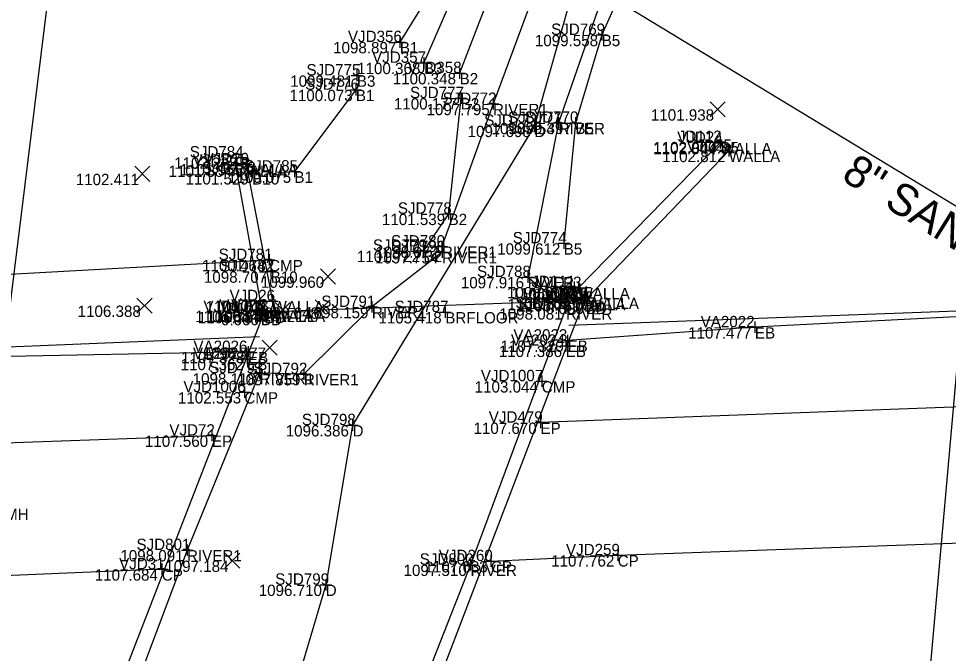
# Model space of a CAD drawing. Extents: x 1629915 to 1630675, y 484401 to 484601.
# Drawn here: x 1630255.7 to 1630337.7, y 484481.8 to 484537.9 of the extents above; entities that cross this region are included whole.
import ezdxf

# ---------------------------------------------------------------- set-up
doc = ezdxf.new("R2010")
doc.units = 0
for name, color, linetype in [('BR_X_Sub_Foot_Object', 7, 'Continuous'), ('BR_X_Sub_Object', 7, 'Continuous'), ('BR_X_SV_Abut', 7, 'Continuous'), ('BR_X_SV_Abut_Text', 7, 'Continuous'), ('BR_X_SV_Deck_Floor', 7, 'Continuous'), ('BR_X_SV_Deck_Top', 7, 'Continuous'), ('DR_X_Ditch', 7, 'Continuous'), ('DR_X_Storm_Sewer', 7, 'Continuous'), ('HY_X_Water_Edge', 7, 'Continuous'), ('PV_X_COP', 7, 'Continuous'), ('PV_X_EOP', 7, 'Continuous'), ('PV_X_Shoulder_Aggregate', 7, 'Continuous'), ('RD_X_GR_Rt', 7, 'Continuous'), ('SV_X_Break_Lines', 7, 'Continuous'), ('SV_X_Random_Point', 7, 'Continuous'), ('SV_X_Shot_Marker', 7, 'Continuous'), ('SV_X_Text_Comment', 7, 'Continuous'), ('SV_X_Text_Elevation', 7, 'Continuous'), ('SV_X_Text_Name', 7, 'Continuous'), ('TX_X_20', 7, 'Continuous'), ('UT_X_Sanitary_Line', 7, 'Continuous')]:
    doc.layers.add(name, color=color, linetype=linetype)

msp = doc.modelspace()

# ---------------------------------------------------------------- linework, layer by layer
at = {"layer": 'BR_X_Sub_Foot_Object'}
msp.add_line((1630334.981, 484467.226), (1630346.372, 484596.321), dxfattribs=at)
at = {"layer": 'BR_X_SV_Abut'}
msp.add_line((1630318.36, 484526.182), (1630305.897, 484513.214), dxfattribs=at)
for points in [[(1630305.897, 484513.214), (1630304.711, 484513.112), (1630305.093, 484514.078), (1630317.606, 484526.882), (1630318.36, 484526.182)], [(1630277.181, 484512.086), (1630274.846, 484524.883), (1630275.777, 484525.003), (1630278.092, 484512.916), (1630278.21, 484512.086)]]:
    msp.add_lwpolyline(points, dxfattribs=at)
at = {"layer": 'BR_X_SV_Deck_Floor'}
msp.add_line((1630293.34, 484511.948), (1630293.34, 484511.948), dxfattribs=at)
at = {"layer": 'BR_X_SV_Deck_Top'}
msp.add_lwpolyline([(1630288.791, 484468.471), (1630260.332, 484468), (1630277.393, 484511.967), (1630305.582, 484512.994), (1630288.334, 484467.836)], dxfattribs=at)
at = {"layer": 'DR_X_Ditch'}
msp.add_lwpolyline([(1630312.285, 484563.174), (1630306.638, 484548.008), (1630304.593, 484540.369), (1630301.212, 484528.393), (1630285.162, 484501.971), (1630282.791, 484487.89), (1630276.09, 484465.226), (1630270.913, 484444.523), (1630257.639, 484422.19), (1630254.188, 484411.475)], dxfattribs=at)
at = {"layer": 'DR_X_Storm_Sewer'}
msp.add_line((1630034.139, 484503.088), (1630277.798, 484516.548), dxfattribs=at)
at = {"layer": 'HY_X_Water_Edge'}
for points in [[(1630309.149, 484564.014), (1630303.907, 484548.371), (1630301.335, 484540.498), (1630297.554, 484530.327), (1630293.047, 484517.737), (1630293.065, 484517.242), (1630286.863, 484512.402), (1630280.864, 484506.48), (1630276.95, 484506.557), (1630270.552, 484490.946), (1630261.424, 484466.626), (1630255.81, 484461.657), (1630255.926, 484458.148), (1630258.606, 484455.59), (1630264.105, 484457.697), (1630265.615, 484457.846), (1630266.742, 484455.334), (1630264.827, 484450.845), (1630263.176, 484437.258), (1630258.725, 484424.768), (1630254.124, 484415.998)], [(1630315.117, 484563.934), (1630310.133, 484547.118), (1630307.022, 484539.287), (1630303.337, 484528.643), (1630300.614, 484515.043), (1630303.987, 484512.284), (1630295.569, 484489.654), (1630286.814, 484467.342), (1630288.813, 484458.618), (1630286.633, 484457.39), (1630280.042, 484444.765), (1630267.68, 484419.987), (1630256.457, 484407.968)]]:
    msp.add_lwpolyline(points, dxfattribs=at)
at = {"layer": 'PV_X_COP'}
for points in [[(1630297.366, 484489.973), (1630308.553, 484490.492), (1630361.839, 484492.402), (1630403.565, 484493.662), (1630440.464, 484494.931), (1630486.149, 484496.207), (1630529.234, 484497.459), (1630568.325, 484498.484), (1630611.926, 484499.834), (1630649.713, 484500.97)], [(1630268.327, 484489.246), (1630243.236, 484488.193), (1630219.614, 484487.396), (1630181.886, 484485.929), (1630141.907, 484484.591), (1630101.847, 484483.155), (1630058.972, 484481.674), (1630018.452, 484480.335), (1629978.036, 484478.791), (1629939.203, 484477.211)]]:
    msp.add_lwpolyline(points, dxfattribs=at)
at = {"layer": 'PV_X_EOP'}
for points in [[(1630649.544, 484512.337), (1630611.095, 484510.961), (1630568.311, 484509.618), (1630527.921, 484508.555), (1630486.049, 484507.685), (1630439.965, 484506.412), (1630403.104, 484505.478), (1630361.875, 484504.434), (1630301.74, 484502.192)], [(1629938.787, 484488.624), (1629977.755, 484490.201), (1630018.109, 484491.66), (1630058.596, 484492.972), (1630101.458, 484494.639), (1630141.527, 484496.094), (1630181.4, 484497.615), (1630219.199, 484499.135), (1630242.799, 484500.003), (1630272.749, 484501.051)]]:
    msp.add_lwpolyline(points, dxfattribs=at)
at = {"layer": 'PV_X_Shoulder_Aggregate'}
for points in [[(1630609.295, 484512.622), (1630601.375, 484512.79), (1630594.371, 484513.028), (1630564.661, 484511.714), (1630557.668, 484510.64), (1630535.062, 484510.052), (1630513.96, 484509.735), (1630489.956, 484510.39), (1630468.462, 484511.02), (1630445.091, 484511.198), (1630420.706, 484511.45), (1630393.49, 484511.943), (1630369.145, 484512.288), (1630344.7, 484511.845), (1630320.659, 484510.608), (1630304.125, 484509.436), (1630303.965, 484508.981)], [(1630275.858, 484507.82), (1630275.935, 484508.43), (1630251.773, 484507.981), (1630226.056, 484507.184), (1630204.993, 484506.289), (1630180.178, 484504.732), (1630155.752, 484502.786), (1630130.505, 484501.377), (1630107.341, 484499.869), (1630082.614, 484498.877), (1630057.423, 484497.854), (1630056.684, 484498.178), (1630055.974, 484498.791), (1630036.737, 484497.117), (1630036.516, 484496.78), (1630005.439, 484492.996), (1629981.146, 484491.329), (1629968.094, 484490.842), (1629967.166, 484490.748), (1629965.306, 484491.801), (1629947.85, 484491.524), (1629935.773, 484490.2), (1629921.037, 484489.433)]]:
    msp.add_lwpolyline(points, dxfattribs=at)
at = {"layer": 'RD_X_GR_Rt'}
for points in [[(1630416.419, 484512.818), (1630392.125, 484513.02), (1630367.206, 484513.077), (1630304.229, 484510.755)], [(1630276.942, 484509.755), (1630213.199, 484507.144), (1630188.359, 484506.044), (1630165.142, 484504.69)]]:
    msp.add_lwpolyline(points, dxfattribs=at)
at = {"layer": 'SV_X_Break_Lines'}
for points in [[(1630296.417, 484563.601), (1630295.615, 484557.584), (1630296.178, 484554.459), (1630296.937, 484552.722), (1630292.991, 484547.948), (1630292.183, 484542.654), (1630292.496, 484540.935), (1630289.335, 484535.783)], [(1630304.314, 484563.932), (1630300.799, 484552.969), (1630299.066, 484544.645), (1630294.605, 484533.045)], [(1630314.711, 484561.886), (1630311.942, 484547.182), (1630307.141, 484536.414), (1630304.819, 484528.662), (1630303.788, 484518.017)], [(1630297.86, 484555.334), (1630298.878, 484552.674), (1630295.673, 484546.879), (1630294.364, 484540.646), (1630291.461, 484533.951)], [(1630285.452, 484531.568), (1630280.033, 484524.355)], [(1630294.699, 484530.831), (1630293.632, 484520.628), (1630291.414, 484517.361)]]:
    msp.add_lwpolyline(points, dxfattribs=at)
at = {"layer": 'SV_X_Random_Point'}
for p, q in [((1630316.712, 484529.177), (1630318.045, 484530.512)), ((1630316.712, 484530.512), (1630318.045, 484529.177)), ((1630265.945, 484523.483), (1630267.278, 484524.818)), ((1630265.945, 484524.818), (1630267.278, 484523.483)), ((1630282.319, 484514.424), (1630283.653, 484515.759)), ((1630282.319, 484515.759), (1630283.653, 484514.424)), ((1630266.132, 484511.855), (1630267.465, 484513.19)), ((1630266.132, 484513.19), (1630267.465, 484511.855)), ((1630278.319, 484511.46), (1630279.652, 484512.795)), ((1630278.319, 484512.795), (1630279.652, 484511.46)), ((1630281.851, 484511.691), (1630283.185, 484513.026)), ((1630281.851, 484513.026), (1630283.185, 484511.691)), ((1630277.177, 484508.147), (1630278.51, 484509.482)), ((1630277.177, 484509.482), (1630278.51, 484508.147)), ((1630273.888, 484489.346), (1630275.221, 484490.681)), ((1630273.888, 484490.681), (1630275.221, 484489.346))]:
    msp.add_line(p, q, dxfattribs=at)
at = {"layer": 'SV_X_Shot_Marker'}
for p, q in [((1630289.335, 484536.283), (1630289.335, 484535.283)), ((1630306.641, 484536.414), (1630307.641, 484536.414)), ((1630307.141, 484536.914), (1630307.141, 484535.914)), ((1630307.141, 484536.414), (1630307.141, 484536.414)), ((1630288.835, 484535.783), (1630289.835, 484535.783)), ((1630289.335, 484535.783), (1630289.335, 484535.783)), ((1630290.961, 484533.951), (1630291.961, 484533.951)), ((1630291.461, 484534.451), (1630291.461, 484533.451)), ((1630291.461, 484533.951), (1630291.461, 484533.951)), ((1630285.538, 484533.334), (1630285.538, 484532.334)), ((1630294.105, 484533.045), (1630295.105, 484533.045)), ((1630294.605, 484533.545), (1630294.605, 484532.545)), ((1630294.605, 484533.045), (1630294.605, 484533.045)), ((1630285.038, 484532.834), (1630286.038, 484532.834)), ((1630285.538, 484532.834), (1630285.538, 484532.834)), ((1630284.952, 484531.568), (1630285.952, 484531.568)), ((1630285.452, 484532.068), (1630285.452, 484531.068)), ((1630285.452, 484531.568), (1630285.452, 484531.568)), ((1630294.699, 484531.331), (1630294.699, 484530.331)), ((1630294.199, 484530.831), (1630295.199, 484530.831)), ((1630294.699, 484530.831), (1630294.699, 484530.831)), ((1630297.554, 484530.827), (1630297.554, 484529.827)), ((1630297.054, 484530.327), (1630298.054, 484530.327)), ((1630297.554, 484530.327), (1630297.554, 484530.327)), ((1630301.212, 484528.893), (1630301.212, 484527.893)), ((1630303.337, 484529.143), (1630303.337, 484528.143)), ((1630304.819, 484529.162), (1630304.819, 484528.162)), ((1630300.712, 484528.393), (1630301.712, 484528.393)), ((1630301.212, 484528.393), (1630301.212, 484528.393)), ((1630302.837, 484528.643), (1630303.837, 484528.643)), ((1630303.337, 484528.643), (1630303.337, 484528.643)), ((1630304.319, 484528.662), (1630305.319, 484528.662)), ((1630304.819, 484528.662), (1630304.819, 484528.662)), ((1630317.605, 484527.466), (1630317.605, 484526.466)), ((1630317.606, 484527.382), (1630317.606, 484526.382)), ((1630317.105, 484526.966), (1630318.105, 484526.966)), ((1630317.106, 484526.882), (1630318.106, 484526.882)), ((1630317.605, 484526.966), (1630317.605, 484526.966)), ((1630317.606, 484526.882), (1630317.606, 484526.882)), ((1630318.36, 484526.682), (1630318.36, 484525.682)), ((1630274.787, 484525.596), (1630275.787, 484525.596)), ((1630275.287, 484526.096), (1630275.287, 484525.096)), ((1630275.287, 484525.596), (1630275.287, 484525.596)), ((1630317.86, 484526.182), (1630318.86, 484526.182)), ((1630318.36, 484526.182), (1630318.36, 484526.182)), ((1630274.346, 484524.883), (1630275.346, 484524.883)), ((1630274.846, 484525.383), (1630274.846, 484524.383)), ((1630274.846, 484524.883), (1630274.846, 484524.883)), ((1630275.277, 484525.003), (1630276.277, 484525.003)), ((1630275.777, 484525.503), (1630275.777, 484524.503)), ((1630275.777, 484525.003), (1630275.777, 484525.003)), ((1630280.033, 484524.855), (1630280.033, 484523.855)), ((1630275.806, 484524.208), (1630276.806, 484524.208)), ((1630276.306, 484524.708), (1630276.306, 484523.708)), ((1630276.306, 484524.208), (1630276.306, 484524.208)), ((1630279.533, 484524.355), (1630280.533, 484524.355)), ((1630280.033, 484524.355), (1630280.033, 484524.355)), ((1630293.632, 484521.128), (1630293.632, 484520.128)), ((1630293.132, 484520.628), (1630294.132, 484520.628)), ((1630293.632, 484520.628), (1630293.632, 484520.628)), ((1630293.047, 484518.237), (1630293.047, 484517.237)), ((1630303.788, 484518.517), (1630303.788, 484517.517)), ((1630291.414, 484517.861), (1630291.414, 484516.861)), ((1630292.547, 484517.737), (1630293.547, 484517.737)), ((1630293.047, 484517.737), (1630293.047, 484517.737)), ((1630293.065, 484517.742), (1630293.065, 484516.742)), ((1630303.288, 484518.017), (1630304.288, 484518.017)), ((1630303.788, 484518.017), (1630303.788, 484518.017)), ((1630277.298, 484516.548), (1630278.298, 484516.548)), ((1630277.798, 484517.048), (1630277.798, 484516.048)), ((1630277.798, 484516.548), (1630277.798, 484516.548)), ((1630290.914, 484517.361), (1630291.914, 484517.361)), ((1630291.414, 484517.361), (1630291.414, 484517.361)), ((1630292.565, 484517.242), (1630293.565, 484517.242)), ((1630293.065, 484517.242), (1630293.065, 484517.242)), ((1630277.935, 484516.036), (1630277.935, 484515.036)), ((1630277.435, 484515.536), (1630278.435, 484515.536)), ((1630277.935, 484515.536), (1630277.935, 484515.536)), ((1630300.114, 484515.043), (1630301.114, 484515.043)), ((1630300.614, 484515.543), (1630300.614, 484514.543)), ((1630300.614, 484515.043), (1630300.614, 484515.043)), ((1630304.2, 484514.161), (1630305.2, 484514.161)), ((1630304.7, 484514.661), (1630304.7, 484513.661)), ((1630304.7, 484514.161), (1630304.7, 484514.161)), ((1630305.093, 484514.578), (1630305.093, 484513.578)), ((1630278.092, 484513.416), (1630278.092, 484512.416)), ((1630304.593, 484514.078), (1630305.593, 484514.078)), ((1630304.711, 484513.612), (1630304.711, 484512.612)), ((1630305.093, 484514.078), (1630305.093, 484514.078)), ((1630305.582, 484513.494), (1630305.582, 484512.494)), ((1630305.728, 484513.269), (1630305.728, 484512.269)), ((1630305.897, 484513.714), (1630305.897, 484512.714)), ((1630277.181, 484512.564), (1630277.181, 484511.564)), ((1630277.393, 484512.467), (1630277.393, 484511.467)), ((1630277.592, 484512.916), (1630278.592, 484512.916)), ((1630278.092, 484512.916), (1630278.092, 484512.916)), ((1630278.21, 484512.586), (1630278.21, 484511.586)), ((1630286.863, 484512.902), (1630286.863, 484511.902)), ((1630293.34, 484512.448), (1630293.34, 484511.448)), ((1630303.987, 484512.784), (1630303.987, 484511.784)), ((1630304.211, 484513.112), (1630305.211, 484513.112)), ((1630304.711, 484513.112), (1630304.711, 484513.112)), ((1630305.082, 484512.994), (1630306.082, 484512.994)), ((1630305.228, 484512.769), (1630306.228, 484512.769)), ((1630305.397, 484513.214), (1630306.397, 484513.214)), ((1630305.582, 484512.994), (1630305.582, 484512.994)), ((1630305.728, 484512.769), (1630305.728, 484512.769)), ((1630305.897, 484513.214), (1630305.897, 484513.214)), ((1630276.573, 484511.782), (1630277.573, 484511.782)), ((1630276.681, 484512.064), (1630277.681, 484512.064)), ((1630276.893, 484511.967), (1630277.893, 484511.967)), ((1630277.073, 484512.282), (1630277.073, 484511.282)), ((1630277.073, 484511.782), (1630277.073, 484511.782)), ((1630277.181, 484512.064), (1630277.181, 484512.064)), ((1630277.393, 484511.967), (1630277.393, 484511.967)), ((1630277.71, 484512.086), (1630278.71, 484512.086)), ((1630278.21, 484512.086), (1630278.21, 484512.086)), ((1630286.363, 484512.402), (1630287.363, 484512.402)), ((1630286.863, 484512.402), (1630286.863, 484512.402)), ((1630292.84, 484511.948), (1630293.84, 484511.948)), ((1630293.34, 484511.948), (1630293.34, 484511.948)), ((1630303.487, 484512.284), (1630304.487, 484512.284)), ((1630303.987, 484512.284), (1630303.987, 484512.284)), ((1630320.659, 484511.108), (1630320.659, 484510.108)), ((1630320.159, 484510.608), (1630321.159, 484510.608)), ((1630320.659, 484510.608), (1630320.659, 484510.608)), ((1630303.625, 484509.436), (1630304.625, 484509.436)), ((1630303.965, 484509.481), (1630303.965, 484508.481)), ((1630304.125, 484509.936), (1630304.125, 484508.936)), ((1630304.125, 484509.436), (1630304.125, 484509.436)), ((1630275.435, 484508.43), (1630276.435, 484508.43)), ((1630275.935, 484508.93), (1630275.935, 484507.93)), ((1630275.935, 484508.43), (1630275.935, 484508.43)), ((1630303.465, 484508.981), (1630304.465, 484508.981)), ((1630303.965, 484508.981), (1630303.965, 484508.981)), ((1630275.358, 484507.82), (1630276.358, 484507.82)), ((1630275.858, 484508.32), (1630275.858, 484507.32)), ((1630275.858, 484507.82), (1630275.858, 484507.82)), ((1630276.95, 484507.057), (1630276.95, 484506.057)), ((1630280.864, 484506.98), (1630280.864, 484505.98)), ((1630276.45, 484506.557), (1630277.45, 484506.557)), ((1630276.95, 484506.557), (1630276.95, 484506.557)), ((1630280.364, 484506.48), (1630281.364, 484506.48)), ((1630280.864, 484506.48), (1630280.864, 484506.48)), ((1630301.853, 484506.347), (1630301.853, 484505.347)), ((1630275.613, 484505.379), (1630275.613, 484504.379)), ((1630301.353, 484505.847), (1630302.353, 484505.847)), ((1630301.853, 484505.847), (1630301.853, 484505.847)), ((1630275.113, 484504.879), (1630276.113, 484504.879)), ((1630275.613, 484504.879), (1630275.613, 484504.879)), ((1630301.74, 484502.692), (1630301.74, 484501.692)), ((1630284.662, 484501.971), (1630285.662, 484501.971)), ((1630285.162, 484502.471), (1630285.162, 484501.471)), ((1630285.162, 484501.971), (1630285.162, 484501.971)), ((1630301.24, 484502.192), (1630302.24, 484502.192)), ((1630301.74, 484502.192), (1630301.74, 484502.192)), ((1630272.249, 484501.051), (1630273.249, 484501.051)), ((1630272.749, 484501.551), (1630272.749, 484500.551)), ((1630272.749, 484501.051), (1630272.749, 484501.051)), ((1630270.552, 484491.446), (1630270.552, 484490.446)), ((1630270.052, 484490.946), (1630271.052, 484490.946)), ((1630270.552, 484490.946), (1630270.552, 484490.946)), ((1630297.366, 484490.473), (1630297.366, 484489.473)), ((1630308.053, 484490.492), (1630309.053, 484490.492)), ((1630308.553, 484490.992), (1630308.553, 484489.992)), ((1630308.553, 484490.492), (1630308.553, 484490.492)), ((1630268.327, 484489.746), (1630268.327, 484488.746)), ((1630295.069, 484489.654), (1630296.069, 484489.654)), ((1630295.569, 484490.154), (1630295.569, 484489.154)), ((1630295.569, 484489.654), (1630295.569, 484489.654)), ((1630296.866, 484489.973), (1630297.866, 484489.973)), ((1630297.366, 484489.973), (1630297.366, 484489.973)), ((1630267.827, 484489.246), (1630268.827, 484489.246)), ((1630268.327, 484489.246), (1630268.327, 484489.246)), ((1630282.291, 484487.89), (1630283.291, 484487.89)), ((1630282.791, 484488.39), (1630282.791, 484487.39)), ((1630282.791, 484487.89), (1630282.791, 484487.89))]:
    msp.add_line(p, q, dxfattribs=at)
at = {"layer": 'UT_X_Sanitary_Line'}
msp.add_lwpolyline([(1629930.746, 484483.734), (1630048.132, 484488.308), (1630252.717, 484494.605), (1630261.76, 484567.793), (1630373.422, 484500.095), (1630654.857, 484509.349)], dxfattribs=at)

# ---------------------------------------------------------------- texts
at = {"layer": 'BR_X_Sub_Object'}
for s, p in [('VJD24', (1630313.802, 484526.882)), ('1102.844', (1630311.685, 484525.882)), ('WALLA', (1630317.606, 484525.882)), ('VJD30', (1630271.051, 484524.883)), ('VJD29', (1630272.012, 484525.003)), ('1102.812', (1630312.488, 484525.182)), ('WALLA', (1630318.36, 484525.182)), ('1101.884', (1630268.926, 484523.883)), ('1101.955', (1630269.909, 484524.003)), ('WALLA', (1630274.846, 484523.883)), ('WALLA', (1630275.777, 484524.003)), ('VJD23', (1630301.347, 484514.078)), ('1106.670', (1630299.181, 484513.078)), ('VJD22', (1630300.956, 484513.112)), ('VJD21', (1630302.134, 484513.214)), ('VJD26', (1630274.306, 484512.916)), ('VJD1001', (1630300.222, 484512.994)), ('JD108', (1630301.959, 484512.769)), ('WALLA', (1630305.093, 484513.078)), ('VJD1000', (1630272.001, 484511.967)), ('1106.616', (1630272.19, 484511.916)), ('JD107', (1630273.308, 484511.782)), ('VJD28', (1630273.399, 484512.064)), ('VJD27', (1630274.432, 484512.086)), ('WALLA', (1630278.092, 484511.916)), ('SJD787', (1630288.869, 484511.948)), ('1106.709', (1630298.829, 484512.112)), ('1106.769', (1630299.7, 484511.994)), ('1106.636', (1630299.995, 484512.214)), ('0.000', (1630302.211, 484511.769)), ('WALLA', (1630304.711, 484512.112)), ('BD', (1630305.582, 484511.994)), ('BD', (1630305.728, 484511.769)), ('WALLA', (1630305.897, 484512.214)), ('1106.644', (1630271.261, 484511.064)), ('1106.787', (1630271.499, 484510.967)), ('1106.647', (1630272.316, 484511.086)), ('0.000', (1630273.555, 484510.782)), ('BD', (1630277.073, 484510.782)), ('WALLA', (1630277.181, 484511.064)), ('BD', (1630277.393, 484510.967)), ('WALLA', (1630278.21, 484511.086)), ('1105.418', (1630287.441, 484510.948)), ('BRFLOOR', (1630293.34, 484510.948))]:
    msp.add_text(s, height=1, dxfattribs=at).set_placement(p)
at = {"layer": 'BR_X_SV_Abut_Text'}
msp.add_text('VJD25', height=1, dxfattribs=at).set_placement((1630314.608, 484526.182))
at = {"layer": 'SV_X_Text_Comment'}
for s, p in [('B5', (1630307.141, 484535.414)), ('B1', (1630289.335, 484534.783)), ('B3', (1630291.461, 484532.951)), ('B2', (1630294.605, 484532.045)), ('B3', (1630285.538, 484531.834)), ('B1', (1630285.452, 484530.568)), ('B2', (1630294.699, 484529.831)), ('RIVER1', (1630297.554, 484529.327)), ('D', (1630301.212, 484527.393)), ('RIVER', (1630303.337, 484527.643)), ('B5', (1630304.819, 484527.662)), ('B5', (1630317.605, 484525.966)), ('B', (1630275.287, 484524.596)), ('B10', (1630276.306, 484523.208)), ('B1', (1630280.033, 484523.355)), ('B2', (1630293.632, 484519.628)), ('B2', (1630291.414, 484516.361)), ('RIVER1', (1630293.047, 484516.737)), ('B5', (1630303.788, 484517.017)), ('CMP', (1630277.798, 484515.548)), ('RIVER1', (1630293.065, 484516.242)), ('B10', (1630277.935, 484514.536)), ('RIVER', (1630300.614, 484514.043)), ('B5', (1630304.7, 484513.161)), ('RIVER1', (1630286.863, 484511.402)), ('RIVER', (1630303.987, 484511.284)), ('EB', (1630320.659, 484509.608)), ('EB', (1630304.125, 484508.436)), ('EB', (1630275.935, 484507.43)), ('EB', (1630303.965, 484507.981)), ('EB', (1630275.858, 484506.82)), ('RIVER1', (1630276.95, 484505.557)), ('RIVER1', (1630280.864, 484505.48)), ('CMP', (1630301.853, 484504.847)), ('CMP', (1630275.613, 484503.879)), ('D', (1630285.162, 484500.971)), ('EP', (1630301.74, 484501.192)), ('EP', (1630272.749, 484500.051)), ('SSMH', (1630252.717, 484493.605)), ('RIVER1', (1630270.552, 484489.946)), ('CP', (1630308.553, 484489.492)), ('RIVER', (1630295.569, 484488.654)), ('CP', (1630297.366, 484488.973)), ('CP', (1630268.327, 484488.246)), ('D', (1630282.791, 484486.89))]:
    msp.add_text(s, height=1, dxfattribs=at).set_placement(p)
at = {"layer": 'SV_X_Text_Elevation'}
for s, p in [('1099.558', (1630301.243, 484535.414)), ('1098.897', (1630283.442, 484534.783)), ('1100.368', (1630285.562, 484532.951)), ('1100.348', (1630288.706, 484532.045)), ('1099.481', (1630279.658, 484531.834)), ('1100.073', (1630279.59, 484530.568)), ('1100.177', (1630288.806, 484529.831)), ('1097.795', (1630291.685, 484529.327)), ('1101.938', (1630311.48, 484528.844)), ('1097.698', (1630295.314, 484527.393)), ('1098.454', (1630297.417, 484527.643)), ('1099.397', (1630298.925, 484527.662)), ('1102.000', (1630311.694, 484525.966)), ('1102.222', (1630269.415, 484524.596)), ('1102.411', (1630260.732, 484523.15)), ('1101.529', (1630270.424, 484523.208)), ('1100.075', (1630274.164, 484523.355)), ('1101.539', (1630287.75, 484519.628)), ('1101.722', (1630285.543, 484516.361)), ('1098.072', (1630287.176, 484516.737)), ('1099.612', (1630297.917, 484517.017)), ('1100.464', (1630271.878, 484515.548)), ('1097.754', (1630287.144, 484516.242)), ('1098.707', (1630272.041, 484514.536)), ('1099.960', (1630277.074, 484514.091)), ('1097.916', (1630294.712, 484514.043)), ('1098.000', (1630298.788, 484513.161)), ('1106.388', (1630260.9, 484511.522)), ('1098.613', (1630273.124, 484511.128)), ('1098.648', (1630276.62, 484511.358)), ('1098.159', (1630280.982, 484511.402)), ('1098.081', (1630298.107, 484511.284)), ('1107.477', (1630314.765, 484509.608)), ('1107.320', (1630298.213, 484508.436)), ('1107.328', (1630270.036, 484507.43)), ('1098.477', (1630271.949, 484507.814)), ('1107.386', (1630298.063, 484507.981)), ('1107.362', (1630269.987, 484506.82)), ('1098.118', (1630271.051, 484505.557)), ('1097.859', (1630274.983, 484505.48)), ('1103.044', (1630295.933, 484504.847)), ('1102.553', (1630269.751, 484503.879)), ('1096.386', (1630279.26, 484500.971)), ('1107.670', (1630295.829, 484501.192)), ('1107.560', (1630266.837, 484500.051)), ('1098.091', (1630264.672, 484489.946)), ('1107.762', (1630302.681, 484489.492)), ('1097.184', (1630268.635, 484489.013)), ('1097.510', (1630289.657, 484488.654)), ('1107.633', (1630291.504, 484488.973)), ('1107.684', (1630262.407, 484488.246)), ('1096.710', (1630276.879, 484486.89))]:
    msp.add_text(s, height=1, dxfattribs=at).set_placement(p)
at = {"layer": 'SV_X_Text_Name'}
for s, p in [('SJD769', (1630302.683, 484536.414)), ('VJD356', (1630284.751, 484535.783)), ('VJD357', (1630286.885, 484533.951)), ('SJD775', (1630281.093, 484532.834)), ('VJD358', (1630290.024, 484533.045)), ('SJD776', (1630280.974, 484531.568)), ('SJD777', (1630290.229, 484530.831)), ('SJD772', (1630293.106, 484530.327)), ('SJD770', (1630300.331, 484528.662)), ('SJD773', (1630296.774, 484528.393)), ('SJD771', (1630298.881, 484528.643)), ('JD112', (1630313.864, 484526.966)), ('SJD784', (1630270.79, 484525.596)), ('SJD783', (1630271.867, 484524.208)), ('SJD785', (1630275.588, 484524.355)), ('SJD778', (1630289.157, 484520.628)), ('SJD774', (1630299.291, 484518.017)), ('SJD779', (1630286.956, 484517.361)), ('SJD780', (1630288.559, 484517.737)), ('SJD790', (1630288.576, 484517.242)), ('SJD781', (1630273.342, 484516.548)), ('SJD782', (1630273.487, 484515.536)), ('SJD788', (1630296.139, 484515.043)), ('JD111', (1630300.949, 484514.161)), ('SJD791', (1630282.407, 484512.402)), ('SJD789', (1630299.528, 484512.284)), ('VA2022', (1630315.875, 484510.608)), ('VA2024', (1630299.132, 484508.981)), ('VA2023', (1630299.35, 484509.436)), ('VA2026', (1630271.12, 484508.43)), ('VA2025', (1630271.077, 484507.82)), ('SJD793', (1630272.512, 484506.557)), ('SJD792', (1630276.416, 484506.48)), ('VJD1007', (1630296.479, 484505.847)), ('VJD1006', (1630270.231, 484504.879)), ('SJD798', (1630280.687, 484501.971)), ('VJD479', (1630297.177, 484502.192)), ('VJD72', (1630268.994, 484501.051)), ('SJD801', (1630266.095, 484490.946)), ('VJD259', (1630303.989, 484490.492)), ('SJD800', (1630291.081, 484489.654)), ('VJD260', (1630292.773, 484489.973)), ('VJD31', (1630264.564, 484489.246)), ('SJD799', (1630278.333, 484487.89))]:
    msp.add_text(s, height=1, dxfattribs=at).set_placement(p)
at = {"layer": 'TX_X_20'}
msp.add_text('8" SAN', height=2.8, rotation=328.1116, dxfattribs=at).set_placement((1630328.179, 484523.681))

doc.saveas('drawing.dxf')
